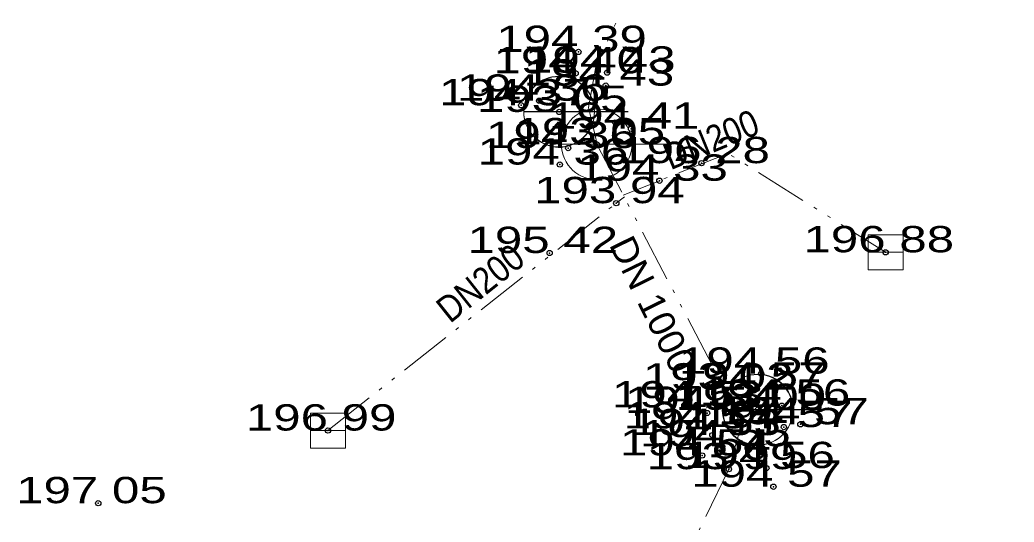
# Model space of a CAD drawing. Extents: x -688177 to -687620, y -1056713 to -1056287.
# Drawn here: x -687941.88 to -687913.53, y -1056473.95 to -1056459.64 of the extents above; entities that cross this region are included whole.
import ezdxf
from ezdxf.enums import TextEntityAlignment as Align

# ---------------------------------------------------------------- set-up
doc = ezdxf.new("R2010")
doc.units = 0
doc.header["$LTSCALE"] = 0.3
doc.header["$PDMODE"] = 32
doc.header["$PDSIZE"] = 0.15
doc.linetypes.add('DASH_DOUBLE_DOT', pattern=[9.2, 5, -1.2, 0.3, -1.2, 0.3, -1.2])
doc.linetypes.add('DOTTED', pattern=[1.5, 0.3, -1.2])
for name, color, linetype in [('1', 7, 'Continuous'), ('16', 7, 'Continuous'), ('18', 7, 'Continuous'), ('3', 7, 'Continuous')]:
    doc.layers.add(name, color=color, linetype=linetype)
for name, color, linetype, lineweight in [('10', 7, 'Continuous', 13), ('12', 7, 'Continuous', 13), ('46', 7, 'DOTTED', 13), ('51', 7, 'DASH_DOUBLE_DOT', 13)]:
    doc.layers.add(name, color=color, linetype=linetype, lineweight=lineweight)

msp = doc.modelspace()

# ---------------------------------------------------------------- linework, layer by layer
at = {"layer": '1'}
for p in [(-687925.95, -1056460.55), (-687925.13, -1056461.14), (-687926.03, -1056461.16), (-687925.17, -1056461.51), (-687927.07, -1056461.94), (-687927.58, -1056462.07), (-687926.5, -1056462.26), (-687924.9, -1056462.56), (-687924.45, -1056462.74), (-687926.24, -1056463.29), (-687925.43, -1056463.18), (-687926.48, -1056463.76), (-687922.44, -1056463.72), (-687923.64, -1056464.22), (-687924.87, -1056464.86), (-687926.77, -1056466.28), (-687917.19, -1056466.26), (-687920.74, -1056469.72), (-687921.77, -1056470.17), (-687920.86, -1056470.15), (-687922.65, -1056470.68), (-687920.84, -1056470.75), (-687920.15, -1056470.63), (-687922.28, -1056470.84), (-687933.09, -1056471.34), (-687922.32, -1056471.28), (-687920.09, -1056471.24), (-687919.62, -1056471.16), (-687922.13, -1056471.47), (-687921.85, -1056471.79), (-687922.42, -1056472.05), (-687921.66, -1056472.44), (-687920.59, -1056472.41), (-687920.39, -1056472.94), (-687939.64, -1056473.41)]:
    msp.add_point(p, dxfattribs=at)
at = {"layer": '10'}
for p, q in [((-687917.69, -1056466.26), (-687916.69, -1056466.26)), ((-687933.59, -1056471.34), (-687932.59, -1056471.34))]:
    msp.add_line(p, q, dxfattribs=at)
for points in [[(-687917.69, -1056466.76), (-687916.69, -1056466.76), (-687916.69, -1056465.76), (-687917.69, -1056465.76)], [(-687933.59, -1056471.84), (-687932.59, -1056471.84), (-687932.59, -1056470.84), (-687933.59, -1056470.84)]]:
    msp.add_lwpolyline(points, close=True, dxfattribs=at)
at = {"layer": '12'}
for p, q in [((-687927.508, -1056462.25), (-687924.532, -1056462.25)), ((-687927.508, -1056462.26), (-687924.532, -1056462.26)), ((-687926.438, -1056463.18), (-687923.462, -1056463.18)), ((-687921.848, -1056470.75), (-687918.872, -1056470.75)), ((-687921.838, -1056470.74), (-687918.862, -1056470.74))]:
    msp.add_line(p, q, dxfattribs=at)
for points in [[(-687926.5, -1056461.242), (-687926.605, -1056461.248), (-687926.709, -1056461.264), (-687926.811, -1056461.292), (-687926.91, -1056461.33), (-687927.004, -1056461.377), (-687927.092, -1056461.435), (-687927.174, -1056461.501), (-687927.249, -1056461.576), (-687927.315, -1056461.658), (-687927.373, -1056461.746), (-687927.42, -1056461.84), (-687927.458, -1056461.939), (-687927.486, -1056462.041), (-687927.502, -1056462.145), (-687927.508, -1056462.25), (-687927.502, -1056462.355), (-687927.486, -1056462.46), (-687927.458, -1056462.562), (-687927.42, -1056462.66), (-687927.373, -1056462.754), (-687927.315, -1056462.843), (-687927.249, -1056462.925), (-687927.174, -1056462.999), (-687927.092, -1056463.065), (-687927.004, -1056463.123), (-687926.91, -1056463.171), (-687926.811, -1056463.209), (-687926.709, -1056463.236), (-687926.605, -1056463.252), (-687926.5, -1056463.258), (-687926.395, -1056463.252), (-687926.29, -1056463.236), (-687926.188, -1056463.209), (-687926.09, -1056463.171), (-687925.996, -1056463.123), (-687925.907, -1056463.065), (-687925.825, -1056462.999), (-687925.751, -1056462.925), (-687925.685, -1056462.843), (-687925.627, -1056462.754), (-687925.579, -1056462.66), (-687925.541, -1056462.562), (-687925.514, -1056462.46), (-687925.498, -1056462.355), (-687925.492, -1056462.25), (-687925.498, -1056462.145), (-687925.514, -1056462.041), (-687925.541, -1056461.939), (-687925.579, -1056461.84), (-687925.627, -1056461.746), (-687925.685, -1056461.658), (-687925.751, -1056461.576), (-687925.825, -1056461.501), (-687925.907, -1056461.435), (-687925.996, -1056461.377), (-687926.09, -1056461.33), (-687926.188, -1056461.292), (-687926.29, -1056461.264), (-687926.395, -1056461.248)], [(-687926.5, -1056461.252), (-687926.605, -1056461.258), (-687926.709, -1056461.274), (-687926.811, -1056461.302), (-687926.91, -1056461.34), (-687927.004, -1056461.387), (-687927.092, -1056461.445), (-687927.174, -1056461.511), (-687927.249, -1056461.586), (-687927.315, -1056461.668), (-687927.373, -1056461.756), (-687927.42, -1056461.85), (-687927.458, -1056461.949), (-687927.486, -1056462.051), (-687927.502, -1056462.155), (-687927.508, -1056462.26), (-687927.502, -1056462.365), (-687927.486, -1056462.47), (-687927.458, -1056462.572), (-687927.42, -1056462.67), (-687927.373, -1056462.764), (-687927.315, -1056462.853), (-687927.249, -1056462.935), (-687927.174, -1056463.009), (-687927.092, -1056463.075), (-687927.004, -1056463.133), (-687926.91, -1056463.181), (-687926.811, -1056463.219), (-687926.709, -1056463.246), (-687926.605, -1056463.262), (-687926.5, -1056463.268), (-687926.395, -1056463.262), (-687926.29, -1056463.246), (-687926.188, -1056463.219), (-687926.09, -1056463.181), (-687925.996, -1056463.133), (-687925.907, -1056463.075), (-687925.825, -1056463.009), (-687925.751, -1056462.935), (-687925.685, -1056462.853), (-687925.627, -1056462.764), (-687925.579, -1056462.67), (-687925.541, -1056462.572), (-687925.514, -1056462.47), (-687925.498, -1056462.365), (-687925.492, -1056462.26), (-687925.498, -1056462.155), (-687925.514, -1056462.051), (-687925.541, -1056461.949), (-687925.579, -1056461.85), (-687925.627, -1056461.756), (-687925.685, -1056461.668), (-687925.751, -1056461.586), (-687925.825, -1056461.511), (-687925.907, -1056461.445), (-687925.996, -1056461.387), (-687926.09, -1056461.34), (-687926.188, -1056461.302), (-687926.29, -1056461.274), (-687926.395, -1056461.258)], [(-687925.43, -1056462.172), (-687925.535, -1056462.178), (-687925.639, -1056462.194), (-687925.741, -1056462.222), (-687925.84, -1056462.26), (-687925.934, -1056462.307), (-687926.022, -1056462.365), (-687926.104, -1056462.431), (-687926.179, -1056462.506), (-687926.245, -1056462.588), (-687926.303, -1056462.676), (-687926.35, -1056462.77), (-687926.388, -1056462.869), (-687926.416, -1056462.971), (-687926.432, -1056463.075), (-687926.438, -1056463.18), (-687926.432, -1056463.285), (-687926.416, -1056463.39), (-687926.388, -1056463.492), (-687926.35, -1056463.59), (-687926.303, -1056463.684), (-687926.245, -1056463.773), (-687926.179, -1056463.855), (-687926.104, -1056463.929), (-687926.022, -1056463.995), (-687925.934, -1056464.053), (-687925.84, -1056464.101), (-687925.741, -1056464.139), (-687925.639, -1056464.166), (-687925.535, -1056464.182), (-687925.43, -1056464.188), (-687925.325, -1056464.182), (-687925.22, -1056464.166), (-687925.118, -1056464.139), (-687925.02, -1056464.101), (-687924.926, -1056464.053), (-687924.837, -1056463.995), (-687924.755, -1056463.929), (-687924.681, -1056463.855), (-687924.615, -1056463.773), (-687924.557, -1056463.684), (-687924.509, -1056463.59), (-687924.471, -1056463.492), (-687924.444, -1056463.39), (-687924.428, -1056463.285), (-687924.422, -1056463.18), (-687924.428, -1056463.075), (-687924.444, -1056462.971), (-687924.471, -1056462.869), (-687924.509, -1056462.77), (-687924.557, -1056462.676), (-687924.615, -1056462.588), (-687924.681, -1056462.506), (-687924.755, -1056462.431), (-687924.837, -1056462.365), (-687924.926, -1056462.307), (-687925.02, -1056462.26), (-687925.118, -1056462.222), (-687925.22, -1056462.194), (-687925.325, -1056462.178)], [(-687920.84, -1056469.742), (-687920.945, -1056469.748), (-687921.049, -1056469.764), (-687921.151, -1056469.792), (-687921.25, -1056469.83), (-687921.344, -1056469.877), (-687921.432, -1056469.935), (-687921.514, -1056470.001), (-687921.589, -1056470.076), (-687921.655, -1056470.158), (-687921.713, -1056470.246), (-687921.76, -1056470.34), (-687921.798, -1056470.439), (-687921.826, -1056470.541), (-687921.842, -1056470.645), (-687921.848, -1056470.75), (-687921.842, -1056470.855), (-687921.826, -1056470.96), (-687921.798, -1056471.062), (-687921.76, -1056471.16), (-687921.713, -1056471.254), (-687921.655, -1056471.343), (-687921.589, -1056471.425), (-687921.514, -1056471.499), (-687921.432, -1056471.565), (-687921.344, -1056471.623), (-687921.25, -1056471.671), (-687921.151, -1056471.709), (-687921.049, -1056471.736), (-687920.945, -1056471.752), (-687920.84, -1056471.758), (-687920.735, -1056471.752), (-687920.63, -1056471.736), (-687920.528, -1056471.709), (-687920.43, -1056471.671), (-687920.336, -1056471.623), (-687920.247, -1056471.565), (-687920.165, -1056471.499), (-687920.091, -1056471.425), (-687920.025, -1056471.343), (-687919.967, -1056471.254), (-687919.919, -1056471.16), (-687919.881, -1056471.062), (-687919.854, -1056470.96), (-687919.838, -1056470.855), (-687919.832, -1056470.75), (-687919.838, -1056470.645), (-687919.854, -1056470.541), (-687919.881, -1056470.439), (-687919.919, -1056470.34), (-687919.967, -1056470.246), (-687920.025, -1056470.158), (-687920.091, -1056470.076), (-687920.165, -1056470.001), (-687920.247, -1056469.935), (-687920.336, -1056469.877), (-687920.43, -1056469.83), (-687920.528, -1056469.792), (-687920.63, -1056469.764), (-687920.735, -1056469.748)], [(-687920.83, -1056469.732), (-687920.935, -1056469.738), (-687921.039, -1056469.754), (-687921.141, -1056469.782), (-687921.24, -1056469.82), (-687921.334, -1056469.867), (-687921.422, -1056469.925), (-687921.504, -1056469.991), (-687921.579, -1056470.066), (-687921.645, -1056470.148), (-687921.703, -1056470.236), (-687921.75, -1056470.33), (-687921.788, -1056470.429), (-687921.816, -1056470.531), (-687921.832, -1056470.635), (-687921.838, -1056470.74), (-687921.832, -1056470.845), (-687921.816, -1056470.95), (-687921.788, -1056471.052), (-687921.75, -1056471.15), (-687921.703, -1056471.244), (-687921.645, -1056471.333), (-687921.579, -1056471.415), (-687921.504, -1056471.489), (-687921.422, -1056471.555), (-687921.334, -1056471.613), (-687921.24, -1056471.661), (-687921.141, -1056471.699), (-687921.039, -1056471.726), (-687920.935, -1056471.742), (-687920.83, -1056471.748), (-687920.725, -1056471.742), (-687920.62, -1056471.726), (-687920.518, -1056471.699), (-687920.42, -1056471.661), (-687920.326, -1056471.613), (-687920.237, -1056471.555), (-687920.155, -1056471.489), (-687920.081, -1056471.415), (-687920.015, -1056471.333), (-687919.957, -1056471.244), (-687919.909, -1056471.15), (-687919.871, -1056471.052), (-687919.844, -1056470.95), (-687919.828, -1056470.845), (-687919.822, -1056470.74), (-687919.828, -1056470.635), (-687919.844, -1056470.531), (-687919.871, -1056470.429), (-687919.909, -1056470.33), (-687919.957, -1056470.236), (-687920.015, -1056470.148), (-687920.081, -1056470.066), (-687920.155, -1056469.991), (-687920.237, -1056469.925), (-687920.326, -1056469.867), (-687920.42, -1056469.82), (-687920.518, -1056469.782), (-687920.62, -1056469.754), (-687920.725, -1056469.738)]]:
    msp.add_lwpolyline(points, close=True, dxfattribs=at)
at = {"layer": '46', "linetype": 'DASH_DOUBLE_DOT'}
msp.add_line((-687925.44, -1056460.92), (-687925.66, -1056462.13), dxfattribs=at)
at = {"layer": '46'}
msp.add_lwpolyline([(-687845.2, -1056286.72), (-687884.46, -1056373.52), (-687925.44, -1056460.92)], dxfattribs=at)
at = {"layer": '46', "linetype": 'DASH_DOUBLE_DOT'}
for points in [[(-687925.66, -1056462.13), (-687925.41, -1056463.22), (-687921.77, -1056470.17), (-687921.31, -1056471.2)], [(-687921.31, -1056471.2), (-687921.66, -1056472.44), (-687931.26, -1056492.1), (-687931.68, -1056493.1)]]:
    msp.add_lwpolyline(points, dxfattribs=at)
at = {"layer": '51'}
for points in [[(-687917.19, -1056466.26), (-687921.69, -1056463.44), (-687923.64, -1056464.22), (-687924.67, -1056464.63)], [(-687933.09, -1056471.34), (-687924.87, -1056464.86), (-687924.64, -1056464.68)]]:
    msp.add_lwpolyline(points, dxfattribs=at)

# ---------------------------------------------------------------- texts
at = {"layer": '16', "width": 0.9}
for rotation, p in [(22.288, (-687923.324, -1056463.925)), (38.503, (-687929.611, -1056468.304))]:
    msp.add_text('DN200', height=0.75, rotation=rotation, dxfattribs=at).set_placement(p)
at = {"layer": '18', "width": 1.05}
msp.add_text(' DN 1000', height=0.75, rotation=296.173, dxfattribs=at).set_placement((-687925.218, -1056465.778))
at = {"layer": '3', "width": 1.4}
for s, p in [('194 39 ', (-687925.95, -1056460.55)), ('194 40 ', (-687926.03, -1056461.16)), ('194 43 ', (-687925.13, -1056461.14)), ('194 43 ', (-687925.17, -1056461.51)), ('194 37 ', (-687927.58, -1056462.07)), ('194 36 ', (-687927.07, -1056461.94)), ('193 05 ', (-687926.5, -1056462.26)), ('194 41 ', (-687924.45, -1056462.74)), ('193 05 ', (-687925.43, -1056463.18)), ('194 36 ', (-687926.24, -1056463.29)), ('194 36 ', (-687926.48, -1056463.76)), ('196 28 ', (-687922.44, -1056463.72)), ('194 33 ', (-687923.64, -1056464.22)), ('193 94 ', (-687924.87, -1056464.86)), ('195 42 ', (-687926.77, -1056466.28)), ('196 88 ', (-687917.19, -1056466.26)), ('194 56 ', (-687920.74, -1056469.72)), ('193 02 ', (-687921.77, -1056470.17)), ('194 57 ', (-687920.86, -1056470.15)), ('194 53 ', (-687922.65, -1056470.68)), ('194 54 ', (-687922.28, -1056470.84)), ('193 00 ', (-687920.84, -1056470.75)), ('194 56 ', (-687920.15, -1056470.63)), ('194 57 ', (-687919.62, -1056471.16)), ('196 99 ', (-687933.09, -1056471.34)), ('194 54 ', (-687922.32, -1056471.28)), ('194 53 ', (-687922.13, -1056471.47)), ('194 57 ', (-687920.09, -1056471.24)), ('194 55 ', (-687921.85, -1056471.79)), ('194 54 ', (-687922.42, -1056472.05)), ('193 99 ', (-687921.66, -1056472.44)), ('194 56 ', (-687920.59, -1056472.41)), ('194 57 ', (-687920.39, -1056472.94)), ('197 05 ', (-687939.64, -1056473.41))]:
    msp.add_text(s, height=0.75, dxfattribs=at).set_placement(p, align=Align.CENTER)

doc.saveas('drawing.dxf')
